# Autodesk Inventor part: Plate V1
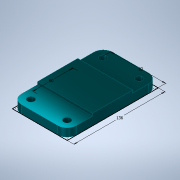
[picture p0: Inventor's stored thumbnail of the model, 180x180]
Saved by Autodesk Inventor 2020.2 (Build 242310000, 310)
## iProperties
Created: 2018-06
Part Number: Plate V1
Material: Aluminum 6061
Document SubType Name: Modeling
Designer: Power User
Density: 2.7 g/cm^3
Appearance: Steel - Polished(2)
Mass: 398.831 g
Surface Area: 289.267 cm^2
Volume: 147.715 cm^3
Author: Power User
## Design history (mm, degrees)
sketch "Sketch1"
  geometry: L1 (41, 68)-(-41, 68); L2 (-41, 68)-(-41, -68); L3 (-41, -68)-(41, -68); L4 (41, -68)-(41, 68); L5 (41, 68)-(-41, -68); L6 (-41, 68)-(41, -68); L7 (-41, -30)-(41, -30); L8 (41, -30)-(41, 30); L9 (41, 30)-(-41, 30); L10 (-41, 30)-(-41, -30); L11 (-41, -30)-(41, 30); L12 (41, -30)-(-41, 30); 1 further point
  constraints: 24 end point, 4 midpoint, 4 parallel, 2 horizontal, 2 perpendicular, 1 collinear
  dimensions: "d0" = 82 distance of L3.end L2.end; "d1" = 136 distance of L2.end L1.end; "d3" = 60 distance between parallel lines of L7 L9
extrude "Extrusion1" new body sketch "Sketch1" distance "d4" = 12; taper "d5" = 0 deg
extrude "Extrusion2" join sketch "Sketch1" distance "d6" = 16; taper "d7" = 0 deg
fillet "Fillet1" dims "d8" = 14
sketch "Sketch3"
  geometry: A1 r 14 centre (-27, -54) between (-41, -54) and (-27, -68) reference; A2 r 14 centre (-27, 54) between (-27, 68) and (-41, 54) reference; A3 r 14 centre (27, 54) between (41, 54) and (27, 68) reference; A4 r 14 centre (27, -54) between (27, -68) and (41, -54) reference; 5 further points
  constraints: 4 coincident
hole "Hole2" sketch "Sketch3" at (-27, -54), (-27, 54), (27, 54), (27, -54) diameter "d16" = 10; stored, may be unused: countersink angle "d20" = 90 deg, drill point angle "d22" = 118 deg; dims "d17" = 6, "d18" = 4, "d19" = 2, "d21" = 8
sketch "Sketch6"
  geometry: L1 (-41, -30)-(41, -30) reference; L2 (41, -30)-(41, 30) reference; 2 further points
  dimensions: "d51" = 30 distance from line of L1 point (0, 0) (= 0.5 x d3); "d52" = 41 distance from line of L2 point (0, 0) (= 0.5 x d0)
hole "Hole5" sketch "Sketch6" at (0, 0) diameter "d53" = 15; stored, may be unused: countersink angle "d57" = 90 deg, drill point angle "d59" = 118 deg; dims "d54" = 6, "d55" = 30, "d56" = 5, "d58" = 8
body "Solid1"
sketch "Sketch4"
  geometry: 1 further point
